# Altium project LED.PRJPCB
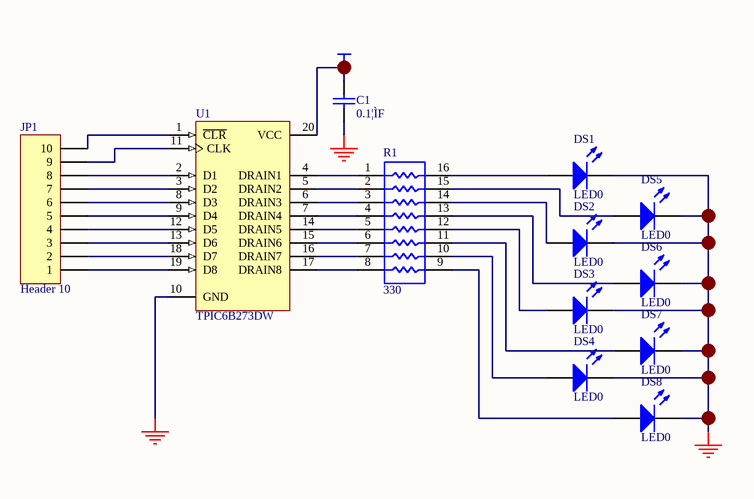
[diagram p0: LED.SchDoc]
1 sheet, 12 parts. Net scope: global (net labels, ports and power ports of the same name join across sheets).
Board file: LED.PCBDOC

## Sheet LED.SchDoc
size B

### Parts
C1  0.1¦ÌF  [RAD-0.3]
DS1  LED0  [LED-0]
DS2  LED0  [LED-0]
DS3  LED0  [LED-0]
DS4  LED0  [LED-0]
DS5  LED0  [LED-0]
DS6  LED0  [LED-0]
DS7  LED0  [LED-0]
DS8  LED0  [LED-0]
JP1  Header 10  [HDR1X10]
R1  330  [SO-G16/G6.9]
U1  TPIC6B273DW  [SO-G20]

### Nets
GND: C1.1 DS1.2(K) DS2.2(K) DS3.2(K) DS4.2(K) DS5.2(K) DS6.2(K) DS7.2(K) DS8.2(K) U1.10(GND)
VCC: C1.2 U1.20(VCC)
NetDS1_1: DS1.1(A) R1.16
NetDS2_1: DS2.1(A) R1.14
NetDS3_1: DS3.1(A) R1.12
NetDS4_1: DS4.1(A) R1.10
NetDS5_1: DS5.1(A) R1.15
NetDS6_1: DS6.1(A) R1.13
NetDS7_1: DS7.1(A) R1.11
NetDS8_1: DS8.1(A) R1.9
NetJP1_1: JP1.1 U1.19(D8)
NetJP1_2: JP1.2 U1.18(D7)
NetJP1_3: JP1.3 U1.13(D6)
NetJP1_4: JP1.4 U1.12(D5)
NetJP1_5: JP1.5 U1.9(D4)
NetJP1_6: JP1.6 U1.8(D3)
NetJP1_7: JP1.7 U1.3(D2)
NetJP1_8: JP1.8 U1.2(D1)
NetJP1_9: JP1.9 U1.11(CLK)
NetJP1_10: JP1.10 U1.1(~{CLR})
NetR1_1: R1.1 U1.4(DRAIN1)
NetR1_2: R1.2 U1.5(DRAIN2)
NetR1_3: R1.3 U1.6(DRAIN3)
NetR1_4: R1.4 U1.7(DRAIN4)
NetR1_5: R1.5 U1.14(DRAIN5)
NetR1_6: R1.6 U1.15(DRAIN6)
NetR1_7: R1.7 U1.16(DRAIN7)
NetR1_8: R1.8 U1.17(DRAIN8)

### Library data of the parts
C1 = Cap: Capacitor; Manufacturer: Generic Components; Class I: Passive; Value: 100pF
DS1-DS8 = LED0: Typical INFRARED GaAs LED; Manufacturer: Generic Components; Class I: Optoelectronic
JP1 = Header 10: Header, 10-Pin; Manufacturer: Generic Components; Class I: Connector
R1 = Res Pack3: Resistor Array; Manufacturer: Generic Components; Class I: Passive
U1 = TPIC6B273DW: Power Logic Octal D-Type Latch; Manufacturer: Texas Instruments; Package Information: Latest Revision: Dec-1998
